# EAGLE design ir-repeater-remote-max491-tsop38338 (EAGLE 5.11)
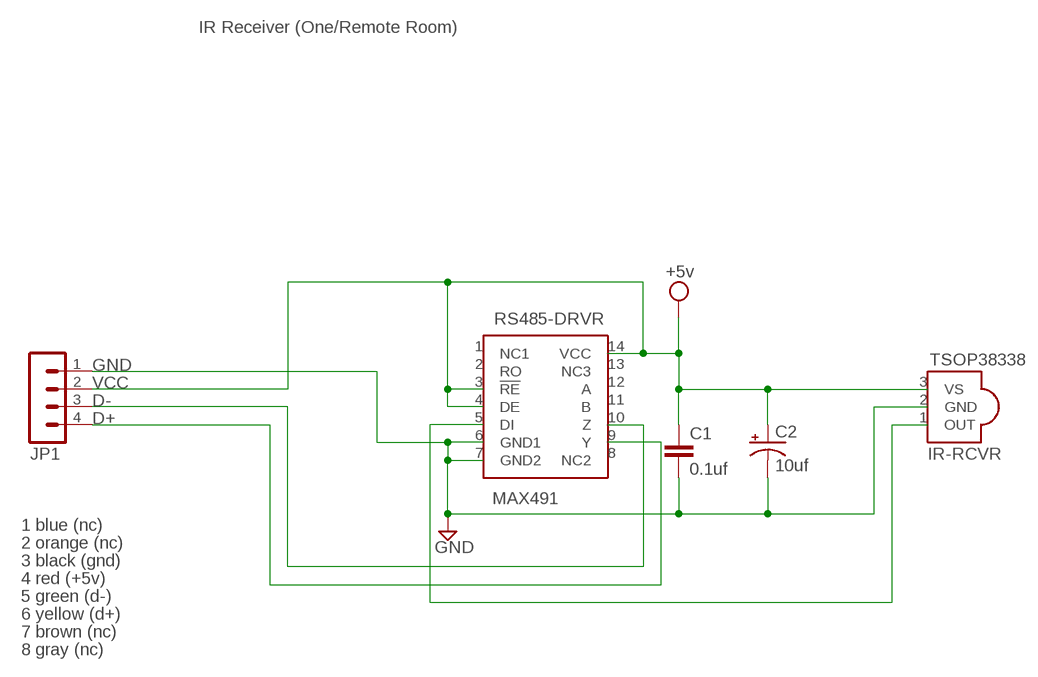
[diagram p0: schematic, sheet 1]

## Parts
C1  0.1uf  C-EU025-030X050  [C025-030X050]
C2  10uf  CPOL-USE2-5  [E2-5]
IR-RCVR  TSOP38338  [TSOP38338]
JP1  MA04-1  [MA04-1]
RS485-DRVR  MAX491  [14DIP]

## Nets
D+: JP1.4 RS485-DRVR.9(Y)
D-: JP1.3 RS485-DRVR.10(Z)
GND: C1.2 C2.- IR-RCVR.2(GND) JP1.1 RS485-DRVR.6(GND1) RS485-DRVR.7(GND2)
N$6: IR-RCVR.1(OUT) RS485-DRVR.5(DI)
VCC: C1.1 C2.+ IR-RCVR.3(VS) JP1.2 RS485-DRVR.3(!RE) RS485-DRVR.4(DE) RS485-DRVR.14(VCC) ; supply symbol labelled +5v
Unconnected: RS485-DRVR.1(NC1) RS485-DRVR.2(RO) RS485-DRVR.8(NC2) RS485-DRVR.11(B) RS485-DRVR.12(A) RS485-DRVR.13(NC3)

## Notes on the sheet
- IR Receiver (One/Remote Room)
- 1 blue (nc)
- 2 orange (nc)
- 3 black (gnd)
- 4 red (+5v)
- 5 green (d-)
- 6 yellow (d+)
- 7 brown (nc)
- 8 gray (nc)

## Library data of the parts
C1 = rcl:C-EU: CAPACITOR, European symbol
C2 = rcl:CPOL-US: POLARIZED CAPACITOR, American symbol
IR-RCVR = trl:TSOP38338
JP1 = con-lstb:MA04-1: PIN HEADER; OC_FARNELL: unknown; OC_NEWARK: unknown
RS485-DRVR = trl:MAX491

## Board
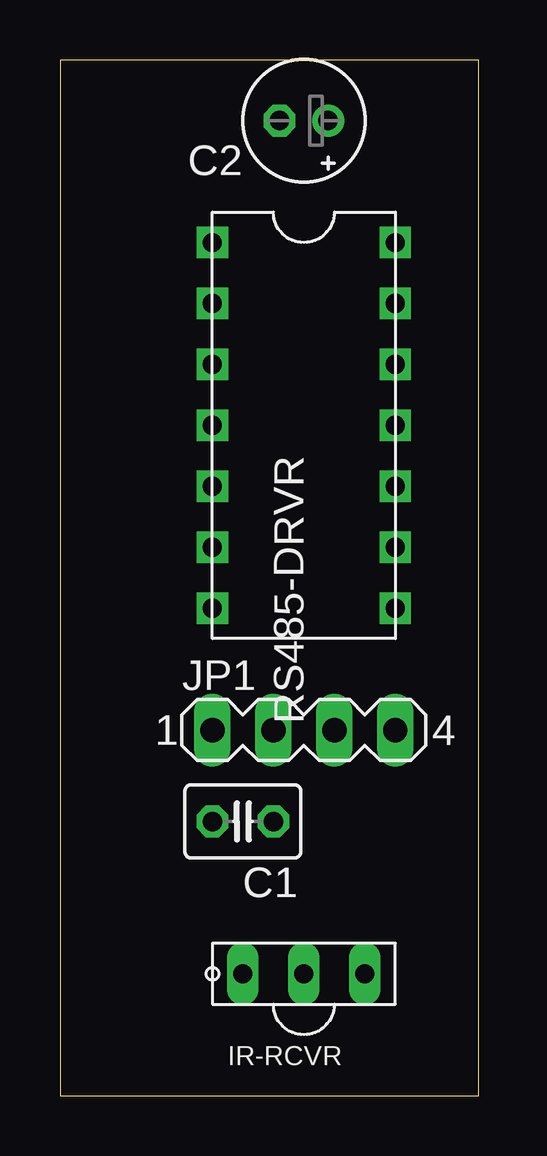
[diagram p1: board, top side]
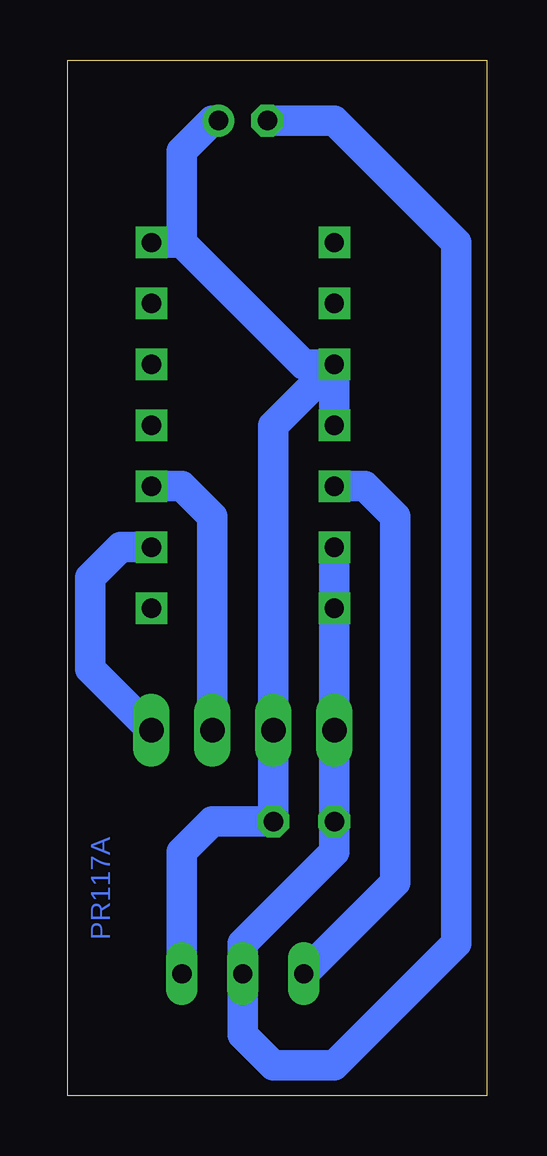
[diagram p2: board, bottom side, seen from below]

Size 17.45 x 43.17 mm. Coordinates in mm from the lower left corner, seen from the top.
Outline: 0,0 17.45,0 17.45,43.17 0,43.17 0,0
Copper layers (1*16): Top 0.035mm / dielectric 1.5mm / Bottom 0.035mm
Design rules "default": minimum track width 10mil, minimum drill 24mil, track to track 8mil, track to pad 8mil, pad to pad 8mil, via to via 8mil, smd to smd 8mil, copper to edge 40mil, drill to drill 8mil, minimum pad ring 10mil, minimum via ring 8mil, stop-mask expansion 4mil, vias tented up to drill 0mil, thermal gap 10mil

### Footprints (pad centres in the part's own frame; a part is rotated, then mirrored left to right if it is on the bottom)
C025-030X050 = drill 0.813 octagon: 1 -1.27,0; 2 1.27,0
E2-5 = drill 0.813 pad 1.27 round: + -1.016,0 | drill 0.813 pad 1.27 octagon: - 1.016,0
TSOP38338 = drill 0.8 long: 1 -2.54,0; 2 0,0; 3 2.54,0
MA04-1 = drill 1.016 long: 1 -3.81,0; 2 -1.27,0; 3 1.27,0; 4 3.81,0
14DIP = drill 0.8 square: 1 -3.81,7.62; 2 -3.81,5.08; 3 -3.81,2.54; 4 -3.81,0; 5 -3.81,-2.54; 6 -3.81,-5.08; 7 -3.81,-7.62; 8 3.81,-7.62; 9 3.81,-5.08; 10 3.81,-2.54; 11 3.81,0; 12 3.81,2.54; 13 3.81,5.08; 14 3.81,7.62

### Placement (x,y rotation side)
C1  7.62,11.43 180 top
C2  10.16,40.64 180 top
IR-RCVR  10.16,5.08 0 top
JP1  10.16,15.24 0 top
RS485-DRVR  10.16,27.94 0 top

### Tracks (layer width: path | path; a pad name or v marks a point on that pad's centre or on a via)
D+
  Bottom 1.27: JP1.4 16.51,17.78 16.51,21.59 15.24,22.86 RS485-DRVR.9
D-
  Bottom 1.27: JP1.3 11.43,24.13 12.7,25.4 RS485-DRVR.10
GND
  Bottom 1.27: RS485-DRVR.6 RS485-DRVR.7 JP1.1 C1.2 6.35,10.16 7.62,8.89 8.89,7.62 10.16,6.35 IR-RCVR.2 10.16,2.54 8.89,1.27 6.35,1.27 5.08,2.54 1.27,6.35 1.27,35.56 2.54,36.83 6.35,40.64 C2.-
N$6
  Bottom 1.27: IR-RCVR.1 3.81,8.89 3.81,24.13 5.08,25.4 RS485-DRVR.5
VCC
  Bottom 1.27: RS485-DRVR.3 RS485-DRVR.4 | RS485-DRVR.3 8.89,27.94 JP1.2 C1.1 10.16,11.43 11.43,11.43 12.7,10.16 12.7,8.89 IR-RCVR.3 | RS485-DRVR.3 7.62,30.48 12.7,35.56 | 12.7,35.56 RS485-DRVR.14 | C2.+ 11.43,40.64 12.7,39.37 12.7,35.56

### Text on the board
Bottom: PR117A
